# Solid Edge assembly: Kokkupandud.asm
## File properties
Author: Indrek
Template: Normal.asm
Last saved by: if07
Revision: 14
Application: Solid Edge
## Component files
konteineriuks.psm
mootor2.par
korrus2.par
korrus1.par
trepp.par
korrus3.par
Balloon.par
mootor.par
konteiner.par
esiklaas.par
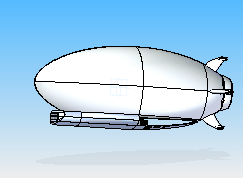
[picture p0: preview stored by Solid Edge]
